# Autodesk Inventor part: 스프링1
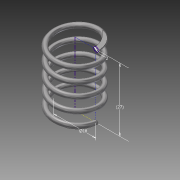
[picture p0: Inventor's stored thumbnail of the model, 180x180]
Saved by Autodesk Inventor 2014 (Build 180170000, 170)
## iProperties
Created: 2016-10
Part Number: 스프링1
Material: Steel, Carbon
Document SubType Name: Modeling
Designer: user
Mass: 6.81325 g
Surface Area: 17.664 cm^2
Volume: 0.865725 cm^3
Density: 7.87 g/cm^3
Appearance: Semi-Polished
Author: user
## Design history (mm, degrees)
sketch "Sketch1"
  geometry: L1 (0, 0)-(-9, 0); L2 (-9, 0)-(-9, -16.67); L3 (-9, -16.67)-(0, -16.67); L4 (0, -16.67)-(0, 0); C1 r 1 at (-9, 0)
  constraints: 8 end point, 2 parallel, 1 centre point, 1 coincident, 1 horizontal, 1 perpendicular
  dimensions: "d0" = 16.66987 distance of L1.end L2.end (derived); "d1" = 2 diameter of C1; "d2" = 18 diameter of L2 L4
coil "Coil1" pitch "d3" = 10; turns "d5" = 5; dims "d4" = 16.66987 (= d0), "d6" = 0, angle "d7" = 90 deg, angle "d8" = 90 deg, "d9" = 0, "d10" = 0
sketch "Sketch2"
  geometry: L1 (10, 0)-(8, 0) reference; L2 (10, 0)-(8, 0) reference; 1 further point
  constraints: 2 horizontal alignment
extrude "Extrusion1" cut sketch "Sketch2" stored distance "d11" = 10; taper "d12" = 0 deg
workplane "Work Plane1"
sketch "Sketch3"
  geometry: L1 (-1, 0)-(1, 0) reference; 1 further point
  constraints: 1 horizontal alignment
extrude "Extrusion2" cut sketch "Sketch3" stored distance "d14" = 10; taper "d15" = 0 deg
body "Solid1"
node "Project Cut Edges1"
node "Project Cut Edges2"
node "Project Cut Edges3"
other parameters: "d13" = 90 deg
